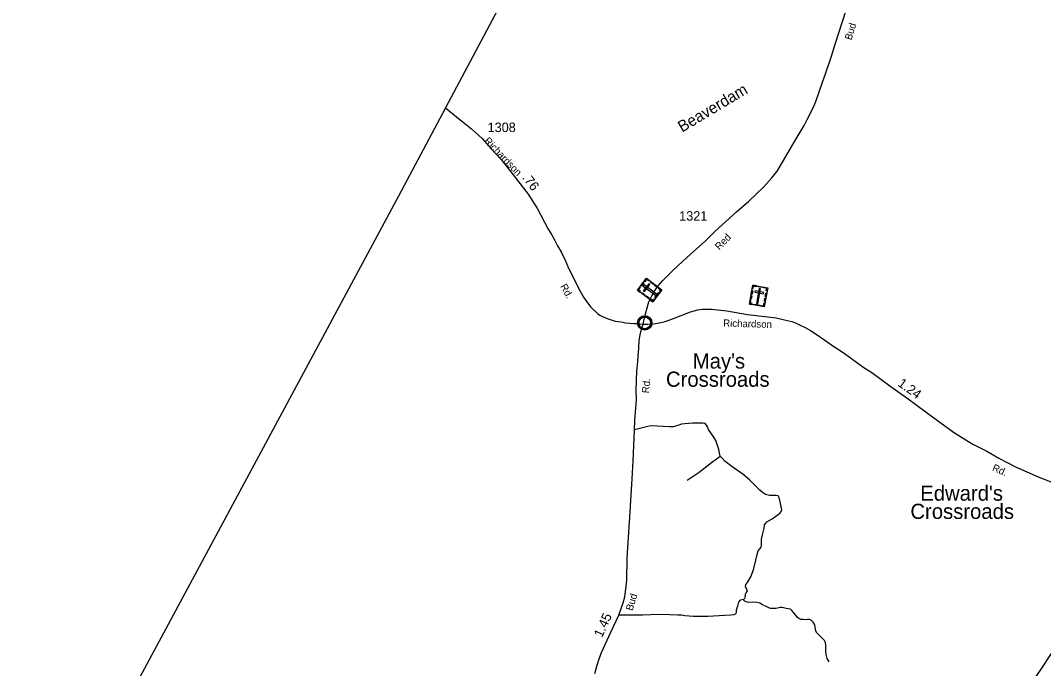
# Model space of a CAD drawing. Extents: x 2220236 to 2384410, y 720751 to 894131.
# Drawn here: x 2253834 to 2267334, y 823438 to 831981 of the extents above; entities that cross this region are included whole.
import ezdxf

# ---------------------------------------------------------------- set-up
doc = ezdxf.new("R2010")
doc.units = 0
doc.layers.add('Default', color=7, linetype='Continuous')

msp = doc.modelspace()

# ---------------------------------------------------------------- linework, layer by layer
at = {"layer": 'Default'}
for points in [[(2293118, 894131), (2291904, 891776), (2258822, 829665), (2255410, 823324), (2242089, 797599), (2231460, 775981), (2225011, 762953), (2220576, 753519)], [(2262049, 827976), (2262075, 828081), (2262127, 828273), (2262164, 828352), (2262196, 828408), (2262251, 828481), (2262310, 828552), (2262440, 828682), (2262576, 828809), (2262717, 828937), (2262868, 829073), (2262996, 829197), (2263284, 829457), (2263443, 829600), (2263539, 829685), (2263644, 829786), (2263749, 829905), (2263817, 829996), (2263845, 830038), (2263888, 830115), (2263964, 830241), (2264011, 830326), (2264094, 830465), (2264177, 830598), (2264214, 830674), (2264294, 830831), (2264330, 830915), (2264417, 831168), (2264458, 831278), (2264534, 831509), (2264583, 831667), (2264864, 832545)], [(2259442, 830829), (2259637, 830672), (2259678, 830641), (2259785, 830553), (2259927, 830424), (2260043, 830295), (2260179, 830148), (2260368, 829905), (2260533, 829691), (2260655, 829497), (2260791, 829240), (2260842, 829159), (2260882, 829087), (2260922, 829010), (2260967, 828929), (2261022, 828823), (2261066, 828716), (2261133, 828590), (2261201, 828445), (2261262, 828334), (2261317, 828258), (2261359, 828201), (2261449, 828118), (2261481, 828097), (2261522, 828074), (2261576, 828052), (2261683, 828019), (2261762, 828006), (2261816, 827997), (2261872, 827989), (2261928, 827988), (2261966, 827984), (2262049, 827976)], [(2262049, 827976), (2262111, 827978), (2262186, 827980), (2262267, 827994), (2262340, 828014), (2262452, 828051), (2262676, 828138), (2262774, 828165), (2262833, 828173), (2262883, 828175), (2262953, 828175), (2263154, 828155), (2263428, 828104), (2263805, 828059), (2263933, 828032), (2264011, 828011), (2264063, 827994), (2264113, 827968), (2264190, 827933), (2264260, 827893), (2264320, 827856), (2264447, 827767), (2264554, 827690), (2264691, 827604), (2264964, 827408), (2265067, 827339), (2265307, 827164), (2265546, 826992), (2265886, 826743), (2266160, 826546), (2266403, 826394), (2266584, 826302), (2266743, 826209), (2266964, 826096), (2267263, 825965), (2267444, 825894)], [(2261415, 823373), (2261444, 823480), (2261466, 823553), (2261499, 823647), (2261626, 823917), (2261729, 824139), (2261731, 824143), (2261761, 824228), (2261789, 824305), (2261808, 824383), (2261824, 824482), (2261834, 824602), (2261839, 824896), (2261853, 825100), (2261875, 825435), (2261905, 825939), (2261918, 826175), (2261936, 826584), (2261942, 826708), (2261956, 826876), (2261961, 826978), (2261959, 827100), (2261961, 827240), (2261968, 827356), (2261982, 827482), (2261986, 827557), (2261992, 827655), (2262000, 827760), (2262013, 827837), (2262030, 827913), (2262049, 827976)], [(2263069, 826236), (2263051, 826326), (2263029, 826391), (2263011, 826443), (2262982, 826486), (2262952, 826533), (2262911, 826590), (2262899, 826624), (2262885, 826647), (2262870, 826667), (2262840, 826671), (2262771, 826673), (2262708, 826671), (2262602, 826665), (2262555, 826661), (2262510, 826643), (2262479, 826633), (2262447, 826625), (2262399, 826625), (2262319, 826628), (2262153, 826636), (2262111, 826628), (2262025, 826606), (2261936, 826584)], [(2262630, 825921), (2262791, 826025), (2262952, 826153), (2263069, 826236)], [(2263373, 824348), (2263397, 824370), (2263401, 824377), (2263399, 824391), (2263401, 824403), (2263403, 824419), (2263411, 824435), (2263423, 824452), (2263428, 824456), (2263415, 824492), (2263407, 824505), (2263403, 824519), (2263407, 824545), (2263427, 824572), (2263476, 824653), (2263511, 824755), (2263539, 824866), (2263554, 824939), (2263568, 824988), (2263592, 825015), (2263606, 825039), (2263613, 825065), (2263611, 825098), (2263611, 825143), (2263627, 825198), (2263647, 825287), (2263653, 825332), (2263669, 825356), (2263684, 825372), (2263714, 825391), (2263753, 825413), (2263802, 825446), (2263832, 825466), (2263857, 825490), (2263873, 825509), (2263879, 825525), (2263875, 825553), (2263857, 825637), (2263846, 825691), (2263836, 825708), (2263826, 825714), (2263808, 825718), (2263761, 825718), (2263720, 825720), (2263663, 825734), (2263627, 825757), (2263592, 825787), (2263541, 825838), (2263452, 825925), (2263364, 826002), (2263240, 826088), (2263135, 826165), (2263087, 826214), (2263069, 826236)], [(2263373, 824348), (2263336, 824338), (2263322, 824328), (2263310, 824312), (2263295, 824261), (2263279, 824206), (2263279, 824179), (2263275, 824165), (2263263, 824153), (2263247, 824145), (2263206, 824139), (2263122, 824135), (2262907, 824125), (2262801, 824123), (2262716, 824125), (2262602, 824133), (2262555, 824139), (2262508, 824143), (2262401, 824145), (2262256, 824149), (2262047, 824143), (2261819, 824143), (2261729, 824139)], [(2264507, 823525), (2264479, 823570), (2264465, 823621), (2264459, 823667), (2264461, 823742), (2264457, 823781), (2264444, 823805), (2264430, 823822), (2264398, 823850), (2264369, 823883), (2264337, 823913), (2264328, 823936), (2264320, 823982), (2264314, 824015), (2264294, 824049), (2264271, 824072), (2264247, 824082), (2264221, 824082), (2264192, 824080), (2264160, 824082), (2264133, 824086), (2264107, 824098), (2264084, 824116), (2264060, 824145), (2264034, 824177), (2264013, 824204), (2263993, 824218), (2263968, 824224), (2263938, 824228), (2263903, 824236), (2263879, 824242), (2263857, 824240), (2263824, 824234), (2263800, 824230), (2263771, 824228), (2263733, 824230), (2263702, 824240), (2263665, 824259), (2263627, 824279), (2263590, 824299), (2263552, 824307), (2263495, 824314), (2263456, 824309), (2263428, 824312), (2263399, 824322), (2263385, 824334), (2263373, 824348)], [(2264779, 821133), (2264847, 821163), (2264939, 821220), (2265054, 821300), (2265270, 821442), (2265375, 821527), (2265404, 821550), (2265515, 821665), (2265582, 821732), (2265653, 821814), (2265710, 821874), (2265801, 821966), (2265910, 822071), (2266029, 822190), (2266255, 822397), (2266332, 822473), (2266451, 822570), (2266580, 822681), (2266981, 823013), (2267068, 823104), (2267109, 823150), (2267143, 823198), (2267318, 823454), (2267503, 823736)]]:
    msp.add_lwpolyline(points, dxfattribs=at)
for points in [[(2261974, 828426), (2262094, 828585), (2262297, 828431), (2262177, 828272)], [(2262009, 828400), (2262016, 828409), (2261990, 828428), (2262014, 828461), (2262006, 828467), (2261974, 828426)], [(2262019, 828485), (2262050, 828526), (2262059, 828519), (2262028, 828478)], [(2262063, 828495), (2262052, 828480), (2262214, 828358), (2262225, 828373)], [(2262053, 828417), (2262068, 828406), (2262139, 828500), (2262124, 828511)], [(2262129, 828559), (2262122, 828550), (2262097, 828569), (2262072, 828537), (2262063, 828543), (2262094, 828585)], [(2262180, 828505), (2262146, 828532), (2262153, 828541), (2262187, 828514)], [(2262233, 828466), (2262198, 828492), (2262205, 828501), (2262240, 828475)], [(2262277, 828405), (2262268, 828411), (2262281, 828429), (2262249, 828453), (2262256, 828462), (2262297, 828431)], [(2263499, 828493), (2263695, 828456), (2263648, 828206), (2263453, 828243)], [(2263491, 828450), (2263503, 828448), (2263508, 828480), (2263548, 828473), (2263550, 828483), (2263499, 828493)], [(2263572, 828479), (2263623, 828470), (2263621, 828459), (2263570, 828468)], [(2263687, 828414), (2263676, 828416), (2263682, 828448), (2263642, 828455), (2263644, 828466), (2263695, 828456)], [(2262068, 828355), (2262033, 828381), (2262040, 828390), (2262075, 828364)], [(2262121, 828314), (2262087, 828341), (2262094, 828350), (2262128, 828324)], [(2262203, 828325), (2262254, 828393), (2262263, 828386), (2262212, 828318)], [(2263465, 828312), (2263473, 828354), (2263485, 828352), (2263477, 828309)], [(2263478, 828378), (2263486, 828420), (2263497, 828418), (2263489, 828375)], [(2263527, 828419), (2263524, 828400), (2263639, 828379), (2263643, 828397)], [(2263601, 828444), (2263583, 828448), (2263545, 828248), (2263564, 828245)], [(2263662, 828344), (2263670, 828387), (2263682, 828385), (2263674, 828342)], [(2262197, 828299), (2262188, 828306), (2262175, 828288), (2262142, 828312), (2262136, 828304), (2262177, 828272)], [(2263485, 828237), (2263487, 828248), (2263466, 828252), (2263473, 828292), (2263462, 828294), (2263452, 828243)], [(2263511, 828243), (2263595, 828228), (2263592, 828217), (2263509, 828232)], [(2263616, 828212), (2263618, 828224), (2263639, 828219), (2263647, 828259), (2263658, 828257), (2263648, 828206)], [(2263650, 828279), (2263658, 828322), (2263669, 828320), (2263662, 828277)], [(2261995, 828007), (2261996, 828012), (2261998, 828019), (2262001, 828026), (2262003, 828032), (2262007, 828037), (2262011, 828043), (2262015, 828047), (2262019, 828051), (2262025, 828056), (2262030, 828060), (2262035, 828063), (2262040, 828065), (2262045, 828067), (2262051, 828069), (2262055, 828070), (2262060, 828071), (2262064, 828072), (2262071, 828072), (2262075, 828072), (2262081, 828072), (2262086, 828071), (2262091, 828070), (2262096, 828069), (2262101, 828067), (2262108, 828064), (2262114, 828060), (2262119, 828057), (2262124, 828053), (2262127, 828050), (2262131, 828045), (2262135, 828040), (2262138, 828036), (2262142, 828031), (2262144, 828026), (2262146, 828021), (2262148, 828016), (2262149, 828011), (2262150, 828005), (2262151, 828000), (2262151, 827994), (2262151, 827989), (2262150, 827983), (2262149, 827977), (2262148, 827971), (2262146, 827965), (2262143, 827960), (2262140, 827954), (2262137, 827949), (2262133, 827944), (2262129, 827940), (2262124, 827935), (2262119, 827930), (2262114, 827927), (2262110, 827924), (2262103, 827921), (2262096, 827919), (2262090, 827917), (2262083, 827916), (2262079, 827915), (2262074, 827915), (2262069, 827915), (2262064, 827915), (2262059, 827916), (2262053, 827918), (2262048, 827919), (2262043, 827921), (2262038, 827923), (2262034, 827925), (2262028, 827929), (2262022, 827933), (2262017, 827938), (2262013, 827943), (2262010, 827947), (2262007, 827951), (2262002, 827958), (2262001, 827961), (2261999, 827965), (2261996, 827974), (2261995, 827981), (2261994, 827986), (2261994, 827992), (2261994, 827997), (2261994, 828003)]]:
    msp.add_lwpolyline(points, close=True, dxfattribs=at)
for radius in [94.3, 76.7]:
    msp.add_circle((2262072, 827994), radius, dxfattribs=at)

# ---------------------------------------------------------------- texts
for s, height, rotation, p in [('Bud', 95, 73.2599, (2264799, 831715)), ('Beaverdam', 150, 30.8888, (2262565, 830502)), ('Richardson', 95, 313.6612, (2259947, 830388)), ('.76', 125, 308.0786, (2260448, 829906)), ('Red', 95, 45.3071, (2263055, 828948)), ('Rd.', 95, 298.4231, (2260954, 828478)), ('Richardson', 95, 358.3416, (2263106, 827946)), ('Rd.', 95, 84.9999, (2262127, 827064)), ('1.24', 125, 324.3516, (2265401, 827173)), ('Rd.', 95, 336.323, (2266649, 826051)), ('Bud', 95, 73.2599, (2261910, 824192)), ('1.45', 125, 65.5988, (2261508, 823837))]:
    msp.add_text(s, height=height, rotation=rotation, dxfattribs=at).set_placement(p)
for s, height, p in [('1308', 125, (2259998, 830510)), ('1321', 125, (2262526, 829342)), ("May's", 200, (2262706, 827392)), ('Crossroads', 200, (2262352, 827152)), ("Edward's", 200, (2265707, 825650)), ('Crossroads', 200, (2265577, 825410))]:
    msp.add_text(s, height=height, dxfattribs=at).set_placement(p)

doc.saveas('drawing.dxf')
